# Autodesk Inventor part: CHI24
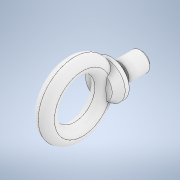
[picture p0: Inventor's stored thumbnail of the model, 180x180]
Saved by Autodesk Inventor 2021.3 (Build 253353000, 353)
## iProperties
Created: 2022-01
Part Number: CHI24
Material: 一般
Description: STEP AP214
Document SubType Name: Modeling
Designer: kengo
Density: 1 g/cm^3
Appearance: 既定
Company: Copyright @ MISUMI Group Inc. All Rights Reserved.
Title: CHI24_20220128151036664.step
Author: ksdm
Revision Number: NONE
Preprocessor: Spatial InterOp 3D
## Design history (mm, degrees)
feature "MI_CHI24_0225160716"
node "ソリッド1"
